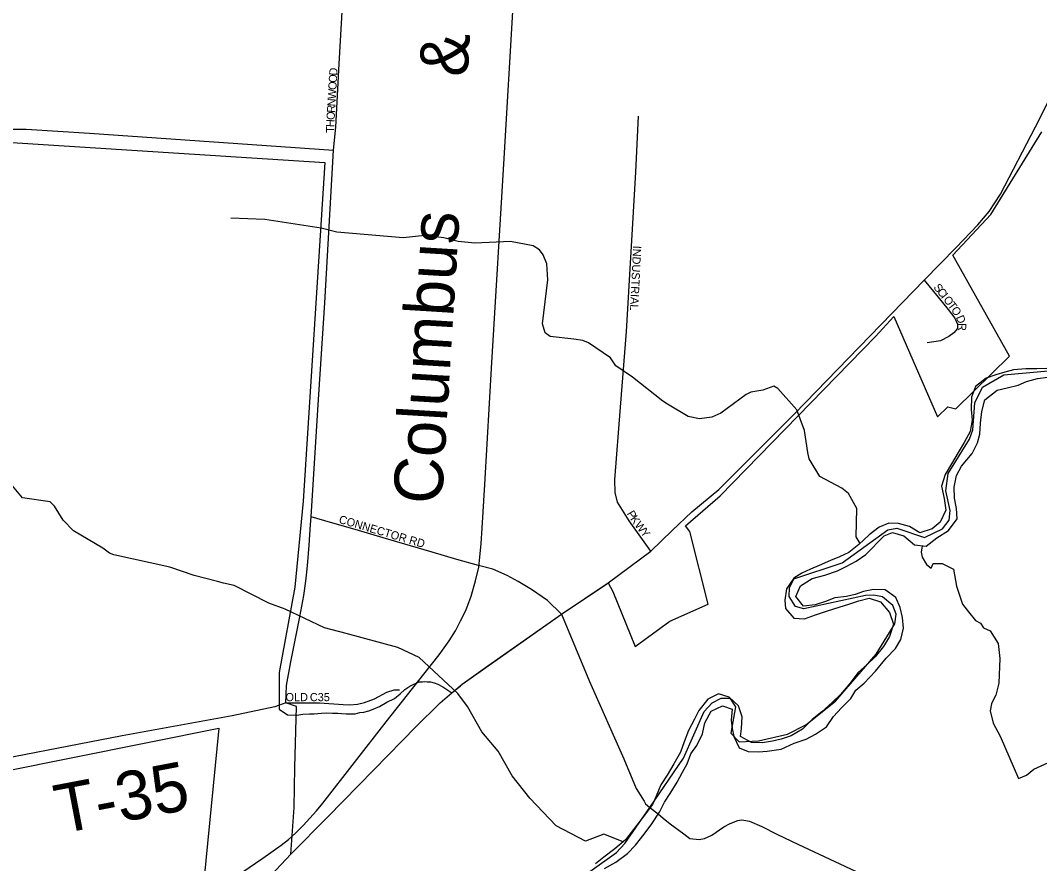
# Model space of a CAD drawing. Extents: x 0 to 40.4, y 0 to 22.
# Drawn here: x 6.701 to 7.886, y 18.932 to 19.912 of the extents above; entities that cross this region are included whole.
import ezdxf

# ---------------------------------------------------------------- set-up
doc = ezdxf.new("R2010")
doc.units = 0
for name, color, linetype in [('GM_P_County_Alignment', 7, 'Continuous'), ('GM_X_City_Street', 7, 'Continuous'), ('GM_X_City_Street_Text', 7, 'Continuous'), ('GM_X_Corporation', 7, 'Continuous'), ('GM_X_Major_River', 7, 'Continuous'), ('GM_X_Minor_River', 7, 'Continuous'), ('GM_X_Rail_Line', 7, 'Continuous'), ('GM_X_Rail_Line_Text', 7, 'Continuous'), ('GM_X_State_Route', 7, 'Continuous'), ('GM_X_Township', 7, 'Continuous'), ('GM_X_Township_Road', 7, 'Continuous'), ('GM_X_Township_Road_Text', 7, 'Continuous')]:
    doc.layers.add(name, color=color, linetype=linetype)

msp = doc.modelspace()

# ---------------------------------------------------------------- linework, layer by layer
at = {"layer": 'GM_P_County_Alignment'}
msp.add_lwpolyline([(7.0156, 18.9428), (7.0197, 18.9968), (7.0203, 19.0434), (7.0221, 19.1144), (7.0098, 19.1185)], dxfattribs=at)
at = {"layer": 'GM_X_City_Street'}
for points in [[(7.0098, 19.1185), (7.0108, 19.1386), (7.0156, 19.1663), (7.0262, 19.2185), (7.0308, 19.2432), (7.0333, 19.26), (7.0351, 19.278), (7.0369, 19.3019), (7.0384, 19.3259), (7.0393, 19.3348), (7.0472, 19.4593), (7.0554, 19.5835), (7.0654, 19.7611), (7.0679, 19.7879), (7.0718, 19.8615), (7.0768, 19.9493), (7.0838, 20.0754), (7.0996, 20.3723), (7.1013, 20.4032)], [(6.2498, 20.2011), (6.296, 20.166), (6.3199, 20.1487), (6.364, 20.1154), (6.4116, 20.0767), (6.4466, 20.0492), (6.4587, 20.036), (6.4681, 20.0231), (6.4842, 19.9981), (6.5013, 19.9731), (6.5145, 19.9536), (6.5241, 19.9412), (6.5642, 19.8984), (6.594, 19.8649), (6.6301, 19.8274), (6.6555, 19.8037), (6.6684, 19.7925), (6.6763, 19.7881), (6.6859, 19.7856), (6.7077, 19.7856), (6.7817, 19.781), (7.0654, 19.7611)], [(7.4343, 19.2951), (7.409, 19.3301), (7.3956, 19.3518), (7.3927, 19.3631), (7.3923, 19.3777), (7.399, 19.4622), (7.4061, 19.5503), (7.4169, 19.7356), (7.42, 19.8009)], [(7.7521, 19.6099), (7.7685, 19.5902), (7.78, 19.5761), (7.7879, 19.5657), (7.7911, 19.5588), (7.7909, 19.5537), (7.7869, 19.5489), (7.781, 19.5444), (7.7712, 19.5396), (7.7558, 19.5372)], [(7.3304, 19.2218), (7.314, 19.2377), (7.2954, 19.2505), (7.2802, 19.2598), (7.2674, 19.2668), (7.2507, 19.2738), (7.234, 19.2781), (7.2088, 19.2851), (7.1801, 19.2936), (7.123, 19.3103), (7.0904, 19.32), (7.0617, 19.3281), (7.0393, 19.3348)], [(7.0098, 19.1185), (7.023, 19.1185), (7.0388, 19.1187), (7.0489, 19.1186), (7.0766, 19.1165), (7.0844, 19.1164), (7.0931, 19.1172), (7.1015, 19.1189), (7.1129, 19.1232), (7.1274, 19.1311), (7.136, 19.1337), (7.142, 19.1337)]]:
    msp.add_lwpolyline(points, dxfattribs=at)
at = {"layer": 'GM_X_Corporation'}
for points in [[(6.6852, 19.7705), (7.0552, 19.7467), (7.0302, 19.353), (7.0204, 19.253), (7.002, 19.1538), (7.002, 19.1113), (7.0118, 19.1048), (7.0227, 19.1044), (7.0297, 19.1055), (7.0373, 19.1059), (7.043, 19.1059), (7.0512, 19.1064), (7.0572, 19.1068), (7.0641, 19.1064), (7.0704, 19.1065), (7.0746, 19.1062), (7.0799, 19.1058), (7.084, 19.1058), (7.0905, 19.1058), (7.0958, 19.1072), (7.1006, 19.1079), (7.1064, 19.1093), (7.1114, 19.1112), (7.1189, 19.1145), (7.1274, 19.1192), (7.1364, 19.1238), (7.143, 19.1292), (7.1483, 19.1339), (7.1541, 19.1378), (7.1589, 19.1402), (7.1621, 19.1418), (7.1649, 19.1428), (7.1689, 19.1431), (7.1711, 19.1434), (7.1742, 19.1431), (7.178, 19.1428), (7.1825, 19.142), (7.1865, 19.1403), (7.1923, 19.1373), (7.203, 19.1301), (7.2151, 19.1402), (7.3304, 19.2218), (7.3849, 19.2581), (7.39, 19.2479), (7.4161, 19.1839), (7.4565, 19.2134), (7.501, 19.2334), (7.4797, 19.3179), (7.4748, 19.3245), (7.5149, 19.3594), (7.6957, 19.5447), (7.7171, 19.5678), (7.7676, 19.4512), (7.7798, 19.4627), (7.7891, 19.4606), (7.8514, 19.5218), (7.7857, 19.6391), (7.8299, 19.6864), (7.8892, 19.7826)], [(6.5092, 19.0041), (6.932, 19.0891), (6.9079, 18.8445), (6.9043, 18.8333), (6.884, 18.7254), (6.9024, 18.7239), (6.847, 18.3381), (6.762, 18.0358), (6.7525, 17.9998), (6.7914, 17.9976), (6.7869, 18.0259), (6.7892, 18.0906), (6.8137, 18.0894), (6.8144, 18.0919), (6.981, 18.0803), (6.9762, 17.9874), (7.435, 17.962), (7.431, 17.8767)]]:
    msp.add_lwpolyline(points, dxfattribs=at)
at = {"layer": 'GM_X_Major_River'}
for points in [[(7.8832, 19.5068), (7.8704, 19.5069), (7.856, 19.5058), (7.8462, 19.5032), (7.8356, 19.4998), (7.8242, 19.4961), (7.8121, 19.4863), (7.8071, 19.4738), (7.807, 19.4597), (7.8081, 19.4472), (7.8058, 19.434), (7.7989, 19.4211), (7.7917, 19.4097), (7.7841, 19.3965), (7.7768, 19.384), (7.7723, 19.3704), (7.7756, 19.356), (7.7774, 19.3427), (7.7709, 19.3287), (7.7615, 19.3208), (7.7471, 19.3163), (7.735, 19.3235), (7.7225, 19.327), (7.7112, 19.3274), (7.6998, 19.3229), (7.6884, 19.3138), (7.6763, 19.3025), (7.6645, 19.2935), (7.6536, 19.2882), (7.6433, 19.2841), (7.6301, 19.2781), (7.6202, 19.2739), (7.61, 19.2694), (7.6005, 19.2634), (7.5921, 19.2513), (7.5902, 19.238), (7.5909, 19.2282), (7.6007, 19.2171), (7.6132, 19.2163), (7.626, 19.2208), (7.6397, 19.2257), (7.6533, 19.2298), (7.6658, 19.2336), (7.6764, 19.2373), (7.6881, 19.2403), (7.7014, 19.2361), (7.7119, 19.2235), (7.7164, 19.2102), (7.7118, 19.1958), (7.7049, 19.1841), (7.6954, 19.172), (7.6859, 19.1633), (7.6749, 19.1535), (7.6658, 19.1411), (7.6548, 19.1282), (7.6453, 19.1191), (7.6331, 19.1082), (7.6221, 19.0991), (7.6108, 19.0878), (7.5975, 19.0803), (7.5861, 19.0762), (7.5759, 19.0739), (7.5642, 19.0721), (7.5513, 19.0725), (7.5385, 19.0794), (7.5397, 19.0888), (7.5405, 19.1021), (7.5364, 19.115), (7.5254, 19.1253), (7.513, 19.1291), (7.5005, 19.1227), (7.4902, 19.1095), (7.4853, 19.0997), (7.478, 19.0864), (7.473, 19.0732), (7.4688, 19.0611), (7.4612, 19.0478), (7.4532, 19.0346), (7.446, 19.0232), (7.4406, 19.01), (7.4361, 19.0002), (7.4281, 18.9896), (7.4155, 18.9729), (7.4049, 18.9593), (7.3924, 18.9488), (7.3795, 18.939), (7.37, 18.9314)], [(7.895, 19.5075), (7.8832, 19.5068)], [(7.3806, 18.9261), (7.3938, 18.9332), (7.4071, 18.9434), (7.4166, 18.9532), (7.4265, 18.9657), (7.4356, 18.9778), (7.4443, 18.9914), (7.4504, 19.0031), (7.4569, 19.013), (7.4649, 19.0262), (7.471, 19.0379), (7.4767, 19.0478), (7.4809, 19.0591), (7.4878, 19.069), (7.4946, 19.0826), (7.497, 19.0955), (7.5046, 19.1087), (7.5178, 19.1151), (7.5288, 19.1113), (7.5276, 19.0984), (7.5291, 19.0889), (7.5309, 19.0794), (7.5369, 19.0661), (7.5475, 19.0619), (7.5596, 19.0615), (7.5698, 19.0622), (7.5861, 19.0648), (7.6009, 19.0715), (7.6149, 19.0764), (7.6259, 19.0821), (7.6387, 19.0907), (7.6467, 19.1025), (7.6559, 19.1127), (7.6669, 19.1236), (7.6726, 19.1334), (7.6824, 19.1414), (7.6957, 19.1553), (7.7079, 19.1705), (7.7189, 19.1818), (7.725, 19.1924), (7.7281, 19.2053), (7.727, 19.2178), (7.7244, 19.2295), (7.7192, 19.2409), (7.7067, 19.2501), (7.6931, 19.2505), (7.6817, 19.2479), (7.6719, 19.2445), (7.6617, 19.2423), (7.6484, 19.2405), (7.6375, 19.2363), (7.6253, 19.2326), (7.6117, 19.2311), (7.6031, 19.2421), (7.6084, 19.2546), (7.6221, 19.2633), (7.6368, 19.267), (7.6516, 19.2719), (7.6614, 19.2772), (7.6732, 19.2832), (7.6842, 19.2911), (7.7058, 19.3126), (7.7153, 19.3168), (7.7285, 19.3126), (7.741, 19.3023), (7.7546, 19.3007), (7.7671, 19.3105), (7.7804, 19.3188), (7.7906, 19.3324), (7.7899, 19.3445), (7.7873, 19.3567), (7.787, 19.3692), (7.7897, 19.3828), (7.7958, 19.3938), (7.808, 19.4085), (7.8141, 19.421), (7.8171, 19.4309), (7.8179, 19.4438), (7.8191, 19.4574), (7.8226, 19.4707), (7.837, 19.482), (7.8487, 19.485), (7.8616, 19.488), (7.8711, 19.4921), (7.8839, 19.4955), (7.8961, 19.4973)]]:
    msp.add_lwpolyline(points, dxfattribs=at)
at = {"layer": 'GM_X_Minor_River'}
for points in [[(7.6778, 19.3039), (7.6733, 19.3117), (7.6738, 19.3446), (7.6644, 19.3621), (7.6564, 19.3682), (7.6307, 19.3819), (7.6183, 19.4024), (7.6168, 19.4096), (7.6131, 19.4354), (7.6041, 19.4593), (7.5822, 19.484), (7.5773, 19.4866), (7.5644, 19.4821), (7.5508, 19.4799), (7.5451, 19.4772), (7.5156, 19.4553), (7.5054, 19.4507), (7.491, 19.4489), (7.4778, 19.4516), (7.4536, 19.466), (7.4483, 19.4694), (7.4132, 19.4972), (7.3936, 19.5105), (7.3875, 19.5196), (7.3619, 19.5371), (7.3554, 19.5398), (7.3448, 19.5413), (7.3173, 19.5444), (7.3116, 19.5489), (7.3082, 19.5592), (7.3147, 19.6103), (7.3133, 19.6289), (7.3091, 19.6396), (7.305, 19.6452), (7.2974, 19.6498), (7.2713, 19.6548), (7.2298, 19.653), (7.2101, 19.6549), (7.1935, 19.6591), (7.1715, 19.6618), (7.1462, 19.6592), (7.0691, 19.6658), (7.051, 19.6704), (6.9856, 19.6804), (6.9459, 19.6823)], [(7.4021, 18.957), (7.3796, 18.9657), (7.3584, 18.9578), (7.3244, 18.9757), (7.2935, 19.0076), (7.2731, 19.0338), (7.2569, 19.0622), (7.2377, 19.085), (7.2211, 19.1142), (7.2098, 19.1294), (7.1649, 19.1712), (7.14, 19.183), (7.0799, 19.1991), (7.0549, 19.2059), (7.0089, 19.2276), (6.99, 19.2345), (6.9499, 19.255), (6.9375, 19.2577), (6.9303, 19.2596), (6.9034, 19.2665), (6.8751, 19.2764), (6.8097, 19.2906), (6.8048, 19.2925), (6.7969, 19.2985), (6.7629, 19.3187), (6.7508, 19.3309), (6.741, 19.3472), (6.7357, 19.3521), (6.7036, 19.3571), (6.69, 19.3731)], [(7.7497, 19.3013), (7.7489, 19.2937), (7.75, 19.288), (7.7549, 19.2793), (7.7602, 19.2751), (7.7625, 19.2804), (7.7731, 19.2804), (7.7863, 19.2739), (7.7897, 19.2542), (7.7968, 19.2333), (7.8036, 19.2242), (7.8119, 19.2143), (7.8179, 19.2113), (7.8213, 19.2056), (7.8289, 19.2022), (7.8383, 19.1877), (7.8402, 19.1703), (7.839, 19.1415), (7.8355, 19.1275), (7.8329, 19.1225), (7.8306, 19.1176), (7.8291, 19.1093), (7.8325, 19.0949), (7.8407, 19.0797), (7.8618, 19.0304), (7.8713, 19.0345), (7.8796, 19.0413), (7.897, 19.0493)]]:
    msp.add_lwpolyline(points, dxfattribs=at)
at = {"layer": 'GM_X_Rail_Line'}
msp.add_lwpolyline([(6.9587, 18.9213), (6.9833, 18.9381), (7.0043, 18.9531), (7.0128, 18.9597), (7.0211, 18.9669), (7.0302, 18.976), (7.0457, 18.9929), (7.053, 19.0018), (7.1265, 19.0964), (7.1704, 19.1519), (7.1882, 19.1743), (7.1999, 19.1908), (7.207, 19.2021), (7.2131, 19.2141), (7.2192, 19.2261), (7.2253, 19.2426), (7.2306, 19.2606), (7.2342, 19.2763), (7.2356, 19.2878), (7.2372, 19.3039), (7.2382, 19.3218), (7.2411, 19.3723), (7.2494, 19.5141), (7.2637, 19.7516), (7.2743, 19.9291)], dxfattribs=at)
at = {"layer": 'GM_X_State_Route'}
for points in [[(7.4592, 19.3188), (7.4821, 19.3405), (7.5133, 19.3667), (7.6013, 19.4547), (7.7521, 19.6099), (7.7893, 19.648), (7.8147, 19.6742), (7.8277, 19.69), (7.8409, 19.7099), (7.8818, 19.7884), (7.9183, 19.8609), (8.0322, 20.0867), (8.0488, 20.1183), (8.0619, 20.1422), (8.13, 20.2571), (8.1543, 20.2979), (8.1577, 20.3035)], [(7.2129, 19.1384), (7.2151, 19.1402), (7.2447, 19.1616), (7.3304, 19.2218), (7.3826, 19.2564), (7.3849, 19.2581), (7.4343, 19.2951), (7.4592, 19.3188)], [(7.1892, 19.1185), (7.203, 19.1301), (7.2129, 19.1384)], [(6.9023, 18.7262), (6.9134, 18.784), (6.9189, 18.8049), (6.929, 18.8329), (6.9422, 18.8585), (6.9577, 18.8818), (6.9755, 18.8996), (7.0156, 18.9428), (7.0587, 18.9862), (7.1121, 19.0405), (7.1614, 19.0909), (7.1881, 19.1176), (7.1892, 19.1185)]]:
    msp.add_lwpolyline(points, dxfattribs=at)
at = {"layer": 'GM_X_Township'}
msp.add_lwpolyline([(7.3633, 18.9223), (7.3945, 18.9445), (7.4042, 18.9549), (7.433, 18.9968), (7.4725, 19.0543), (7.4964, 19.1086), (7.5057, 19.1186), (7.5163, 19.1241), (7.5261, 19.1239), (7.5327, 19.1141), (7.5275, 19.0833), (7.5371, 19.0731), (7.5595, 19.0742), (7.5932, 19.082), (7.6147, 19.0929), (7.6492, 19.1204), (7.6965, 19.1751), (7.718, 19.2104), (7.7197, 19.2218), (7.7158, 19.2316), (7.7039, 19.2417), (7.6936, 19.2438), (7.6841, 19.2433), (7.6122, 19.2278), (7.6027, 19.2307), (7.5953, 19.2423), (7.5955, 19.2522), (7.6007, 19.2626), (7.657, 19.2813), (7.7099, 19.3197), (7.7205, 19.3217), (7.7525, 19.3108), (7.7736, 19.321), (7.7811, 19.331), (7.7824, 19.3421), (7.7775, 19.3652), (7.7802, 19.3853), (7.8051, 19.4252), (7.8087, 19.4359), (7.8113, 19.4675), (7.8201, 19.4855), (7.8449, 19.4999), (7.9526, 19.5095)], dxfattribs=at)
at = {"layer": 'GM_X_Township_Road'}
for points in [[(7.3304, 19.2218), (7.3631, 19.1432), (7.4028, 19.0535), (7.4173, 19.0191), (7.4264, 19.0042)], [(7.0098, 19.1185), (6.9971, 19.1141), (6.9476, 19.1035), (6.8196, 19.0802), (6.6311, 19.0439), (6.5915, 19.0309), (6.523, 19.0125), (6.4954, 19.0041), (6.4712, 18.9966), (6.4303, 18.9749), (6.3004, 18.9068), (6.2582, 18.8838), (6.1264, 18.8144), (5.7095, 18.6233)], [(7.4264, 19.0042), (7.4282, 19.0012), (7.433, 18.9968), (7.4427, 18.9894), (7.4485, 18.9846)], [(7.4485, 18.9846), (7.4569, 18.9777), (7.4727, 18.9663), (7.4798, 18.9609), (7.4907, 18.9597), (7.4969, 18.9609), (7.5051, 18.9648), (7.5194, 18.9743), (7.5266, 18.9782), (7.5354, 18.9816), (7.5403, 18.9825), (7.5489, 18.981), (7.5634, 18.9747), (7.5808, 18.9659), (7.6061, 18.9538), (7.7991, 18.8636), (7.8738, 18.8268), (7.9375, 18.8004)]]:
    msp.add_lwpolyline(points, dxfattribs=at)

# ---------------------------------------------------------------- texts
at = {"layer": 'GM_X_City_Street_Text'}
for s, rotation, p in [('D', 86.5886, (7.0696, 19.8477)), ('O', 86.5886, (7.0691, 19.8393)), ('W', 86.6091, (7.0679, 19.8202)), ('O', 86.5886, (7.0686, 19.831)), ('N', 86.5886, (7.0674, 19.8119)), ('R', 86.5979, (7.067, 19.8044)), ('H', 87.1791, (7.0661, 19.7878)), ('O', 86.6104, (7.0665, 19.7961)), ('T', 89.317, (7.066, 19.7812)), ('INDUSTRIAL', 267.2424, (7.4138, 19.6503)), ('S', 308.28, (7.7625, 19.6015)), ('C', 308.2649, (7.7667, 19.5963)), ('I', 308.315, (7.7713, 19.5904)), ('O', 308.2775, (7.7739, 19.5871)), ('T', 307.1322, (7.779, 19.5806)), ('O', 304.6661, (7.783, 19.5754)), ('D', 292.398, (7.7889, 19.5669)), ('R', 268.4453, (7.7918, 19.5603)), ('CONNECTOR RD', 343.551, (7.0708, 19.3279)), ('P', 300.514, (7.4061, 19.3387)), ('K', 305.1974, (7.4099, 19.3323)), ('W', 307.5542, (7.4149, 19.3251)), ('Y', 307.5763, (7.4216, 19.3165)), ('OLD', 0, (7.0095, 19.1205)), ('C35', 0, (7.0378, 19.1205))]:
    msp.add_text(s, height=0.00947, rotation=rotation, dxfattribs=at).set_placement(p)
at = {"layer": 'GM_X_Rail_Line_Text'}
for s, height, rotation, p in [('&', 0.0566, 86.6745, (7.2211, 19.8457)), ('Columbus', 0.05663, 86.4935, (7.1911, 19.3485))]:
    msp.add_text(s, height=height, rotation=rotation, dxfattribs=at).set_placement(p)
at = {"layer": 'GM_X_Township_Road_Text'}
msp.add_text('T-35', height=0.05682, rotation=10.834, dxfattribs=at).set_placement((6.7473, 18.9661))

doc.saveas('drawing.dxf')
